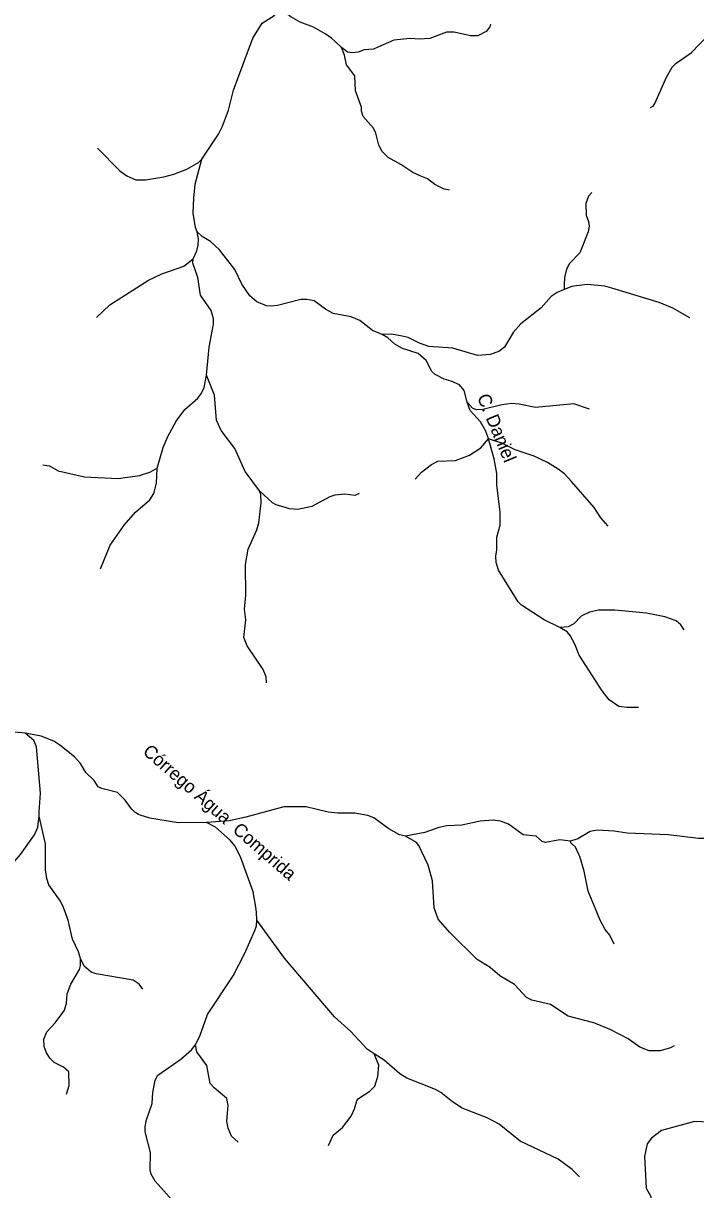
# Model space of a CAD drawing. Extents: x 473.9 to 500, y 7733.1 to 7760.8.
# Drawn here: x 477.9 to 481.99, y 7741.31 to 7748.41 of the extents above; entities that cross this region are included whole.
import ezdxf
from ezdxf.enums import TextEntityAlignment as Align

# ---------------------------------------------------------------- set-up
doc = ezdxf.new("R2010")
doc.units = 0
doc.header["$LTSCALE"] = 0.032
doc.layers.add('61', color=7, linetype='Continuous')
doc.layers.add('7', color=7, linetype='Continuous', lineweight=25)

msp = doc.modelspace()

# ---------------------------------------------------------------- linework, layer by layer
at = {"layer": '7'}
for points in [[(478.9839, 7747.5805), (479.0851, 7747.7324), (479.1095, 7747.7805), (479.1456, 7747.8769), (479.176, 7747.9985), (479.2935, 7748.3153), (479.3509, 7748.4069), (479.4226, 7748.4528), (479.4367, 7748.4688), (479.439, 7748.4833), (479.4278, 7748.51)], [(479.8343, 7748.2586), (479.7962, 7748.2948), (479.7729, 7748.3169), (479.7354, 7748.3421), (479.6641, 7748.3822), (479.5821, 7748.4132), (479.5259, 7748.4455), (479.4621, 7748.4945), (479.4278, 7748.51)], [(480.7404, 7748.4019), (480.7368, 7748.3843), (480.7152, 7748.3569), (480.664, 7748.3307), (480.6197, 7748.3301), (480.5196, 7748.3525), (480.4731, 7748.3532), (480.3712, 7748.3132), (480.3059, 7748.31), (480.2524, 7748.3148), (480.1531, 7748.3044), (480.0553, 7748.2617), (480.0286, 7748.25), (479.9728, 7748.2441), (479.9346, 7748.2314), (479.898, 7748.2267), (479.8705, 7748.2314), (479.8343, 7748.2586)], [(481.7151, 7747.8935), (481.7306, 7747.902), (481.7418, 7747.9179), (481.8131, 7748.078), (481.8468, 7748.1401), (481.8712, 7748.1642), (481.962, 7748.227), (482.0709, 7748.3392)], [(480.4909, 7747.3903), (480.4581, 7747.3968), (480.4029, 7747.425), (480.3579, 7747.46), (480.3175, 7747.477), (480.2684, 7747.4976), (480.1949, 7747.5476), (480.1179, 7747.5898), (480.0814, 7747.6252), (480.0616, 7747.6647), (480.0437, 7747.7371), (480.0297, 7747.7686), (479.9652, 7747.8402), (479.9555, 7747.8715), (479.9554, 7747.8965), (479.9187, 7747.9953), (479.9159, 7748.0862), (479.8643, 7748.1537), (479.8529, 7748.2118), (479.8343, 7748.2586)], [(478.3495, 7747.6474), (478.4855, 7747.5093), (478.5275, 7747.4776), (478.5818, 7747.4545), (478.6415, 7747.4537), (478.7531, 7747.4721), (478.8132, 7747.4882), (478.8919, 7747.5183), (478.9644, 7747.5595), (478.9839, 7747.5805)], [(478.9562, 7747.1379), (478.9452, 7747.1637), (478.9317, 7747.2508), (478.9344, 7747.3428), (478.9429, 7747.4267), (478.9839, 7747.5805)], [(481.3573, 7747.3762), (481.3375, 7747.3538), (481.3221, 7747.3098), (481.324, 7747.2382), (481.3383, 7747.1997), (481.3408, 7747.1715), (481.3353, 7747.1377), (481.2859, 7747.01), (481.2229, 7746.9435), (481.2034, 7746.9095), (481.1909, 7746.8592), (481.1905, 7746.8131), (481.1903, 7746.7868)], [(478.9303, 7746.9724), (478.9533, 7747.0212), (478.9611, 7747.0568), (478.9645, 7747.0933), (478.9562, 7747.1379)], [(480.0823, 7746.5122), (480.022, 7746.5361), (479.945, 7746.5973), (479.8926, 7746.6198), (479.783, 7746.6409), (479.7358, 7746.667), (479.6678, 7746.7162), (479.6239, 7746.7256), (479.5891, 7746.7244), (479.579, 7746.7241), (479.4446, 7746.6889), (479.4052, 7746.6855), (479.377, 7746.6863), (479.3186, 7746.7113), (479.2764, 7746.7479), (479.2282, 7746.8187), (479.184, 7746.9074), (479.0908, 7747.0273), (479.0369, 7747.0782), (478.9854, 7747.1091), (478.9562, 7747.1379)], [(478.3417, 7746.6164), (478.4234, 7746.6923), (478.6596, 7746.8423), (478.7396, 7746.881), (478.874, 7746.9281), (478.9303, 7746.9724)], [(479.0116, 7746.2656), (479.0287, 7746.4345), (479.0494, 7746.5427), (479.0557, 7746.5757), (479.0558, 7746.6085), (479.0415, 7746.6579), (478.9767, 7746.7525), (478.9598, 7746.8596), (478.9293, 7746.9466), (478.9303, 7746.9724)], [(481.1903, 7746.7868), (481.1461, 7746.7678), (481.1101, 7746.7433), (481.0492, 7746.6736), (480.9257, 7746.5773), (480.88, 7746.5236), (480.8271, 7746.4346), (480.791, 7746.4082), (480.7397, 7746.3905), (480.6627, 7746.3841), (480.512, 7746.4298), (480.3661, 7746.4402), (480.3083, 7746.4595), (480.2402, 7746.4932), (480.2025, 7746.5028), (480.1384, 7746.514), (480.0823, 7746.5122)], [(481.9542, 7746.6147), (481.8502, 7746.6728), (481.7676, 7746.708), (481.4801, 7746.7938), (481.4372, 7746.8066), (481.3298, 7746.8163), (481.2474, 7746.8056), (481.2368, 7746.8042), (481.1903, 7746.7868)], [(480.5999, 7746.1013), (480.58, 7746.1723), (480.5523, 7746.205), (480.5014, 7746.2283), (480.459, 7746.2402), (480.4042, 7746.2682), (480.3845, 7746.2865), (480.3497, 7746.3538), (480.3002, 7746.3976), (480.2063, 7746.4279), (480.159, 7746.4543), (480.1166, 7746.4922), (480.0823, 7746.5122)], [(478.712, 7745.6979), (478.7484, 7745.8239), (478.7771, 7745.8924), (478.828, 7745.9848), (478.8801, 7746.0551), (478.9599, 7746.1245), (478.9785, 7746.1485), (478.9981, 7746.1872), (479.0116, 7746.2656)], [(479.3352, 7745.5602), (479.2479, 7745.6783), (479.1845, 7745.8187), (479.1025, 7745.9274), (479.074, 7745.9915), (479.0616, 7746.1432), (479.0116, 7746.2656)], [(480.7298, 7745.8772), (480.713, 7745.9241), (480.6807, 7745.9809), (480.6176, 7746.0492), (480.5999, 7746.1013)], [(481.3431, 7746.058), (481.2482, 7746.0898), (481.0146, 7746.0673), (480.9163, 7746.089), (480.8703, 7746.0915), (480.8105, 7746.0842), (480.6937, 7746.0567), (480.6559, 7746.0546), (480.6317, 7746.0646), (480.5999, 7746.1013)], [(480.2823, 7745.6313), (480.3214, 7745.6738), (480.3823, 7745.7203), (480.4195, 7745.7406), (480.5275, 7745.7463), (480.6132, 7745.7773), (480.6825, 7745.8219), (480.7298, 7745.8772)], [(481.1639, 7744.7282), (481.0676, 7744.7753), (480.9302, 7744.8641), (480.9101, 7744.885), (480.7891, 7745.0777), (480.7747, 7745.1248), (480.7734, 7745.1629), (480.7797, 7745.2019), (480.7798, 7745.2796), (480.8005, 7745.351), (480.8005, 7745.4303), (480.7798, 7745.598), (480.7797, 7745.666), (480.7644, 7745.7558), (480.7298, 7745.8772)], [(481.4576, 7745.3463), (481.4136, 7745.3973), (481.372, 7745.4591), (481.2351, 7745.6178), (481.192, 7745.6632), (481.1535, 7745.6918), (481.0881, 7745.7324), (481.0063, 7745.7708), (480.8922, 7745.8106), (480.8095, 7745.8511), (480.7298, 7745.8772)], [(478.015, 7745.7194), (478.0555, 7745.7136), (478.1092, 7745.6833), (478.2699, 7745.6449), (478.4747, 7745.636), (478.604, 7745.6545), (478.6678, 7745.6752), (478.712, 7745.6979)], [(478.3665, 7745.0863), (478.4255, 7745.2292), (478.5118, 7745.351), (478.5803, 7745.4305), (478.6668, 7745.5068), (478.6917, 7745.5435), (478.7078, 7745.6082), (478.712, 7745.6979)], [(479.3768, 7744.3928), (479.375, 7744.4293), (479.3572, 7744.4737), (479.2605, 7744.6175), (479.2404, 7744.6676), (479.2516, 7744.7764), (479.2436, 7744.8411), (479.2516, 7744.9256), (479.25, 7745.1131), (479.2663, 7745.2048), (479.3187, 7745.3239), (479.3309, 7745.3659), (479.3454, 7745.4868), (479.3421, 7745.539), (479.3352, 7745.5602)], [(479.9424, 7745.5447), (479.9152, 7745.533), (479.8551, 7745.5406), (479.7938, 7745.5342), (479.7628, 7745.5236), (479.653, 7745.4663), (479.5679, 7745.4475), (479.5174, 7745.4508), (479.5052, 7745.4546), (479.4373, 7745.4758), (479.4137, 7745.488), (479.3352, 7745.5602)], [(481.921, 7744.7145), (481.8991, 7744.7449), (481.8718, 7744.7692), (481.8026, 7744.7934), (481.6898, 7744.8158), (481.4971, 7744.8351), (481.3991, 7744.8335), (481.3437, 7744.8225), (481.2922, 7744.7981), (481.2492, 7744.7505), (481.2139, 7744.7323), (481.1639, 7744.7282)], [(481.6423, 7744.2416), (481.5702, 7744.2409), (481.5228, 7744.2483), (481.4633, 7744.2894), (481.4201, 7744.3435), (481.2799, 7744.5595), (481.255, 7744.6268), (481.2269, 7744.6797), (481.2086, 7744.7019), (481.1639, 7744.7282)], [(477.9091, 7744.0852), (477.7182, 7744.103), (477.5626, 7744.1399), (477.3779, 7744.1569), (477.3061, 7744.1712), (477.2072, 7744.2029)], [(477.9926, 7743.5798), (477.9942, 7743.6077), (478.0007, 7743.7196), (477.9766, 7744.0025), (477.9602, 7744.04), (477.9091, 7744.0852)], [(479.0129, 7743.5416), (478.8404, 7743.5394), (478.6664, 7743.5678), (478.6088, 7743.5857), (478.5983, 7743.5913), (478.5786, 7743.6019), (478.5547, 7743.6245), (478.5164, 7743.6786), (478.4705, 7743.7237), (478.3753, 7743.7478), (478.3534, 7743.7587), (478.3275, 7743.797), (478.2778, 7743.8472), (478.245, 7743.9004), (478.2087, 7743.9416), (478.12, 7744.0127), (478.0835, 7744.036), (478.0063, 7744.0677), (477.9091, 7744.0852)], [(480.2235, 7743.4594), (480.1878, 7743.4665), (480.1222, 7743.5032), (480.0306, 7743.57), (479.9934, 7743.5854), (479.9161, 7743.5986), (479.812, 7743.5979), (479.7529, 7743.6039), (479.6191, 7743.6371), (479.4821, 7743.6363), (479.2522, 7743.574), (479.1493, 7743.553), (479.0129, 7743.5416)], [(477.82, 7742.7699), (477.7879, 7742.8106), (477.7771, 7742.8444), (477.7587, 7743.0924), (477.7627, 7743.1596), (477.7808, 7743.218), (477.8021, 7743.2574), (477.8806, 7743.3472), (477.9657, 7743.4661), (477.9848, 7743.514), (477.9926, 7743.5798)], [(478.2456, 7742.7145), (478.2335, 7742.7546), (478.1966, 7742.8315), (478.1707, 7742.9476), (478.1421, 7743.024), (478.1236, 7743.0628), (478.0522, 7743.1627), (478.0405, 7743.2004), (478.0329, 7743.2533), (478.0312, 7743.411), (477.9926, 7743.5798)], [(479.3193, 7742.9473), (479.3172, 7742.9957), (479.3122, 7743.0259), (479.2964, 7743.1208), (479.2193, 7743.3327), (479.1843, 7743.3996), (479.1571, 7743.4349), (479.0674, 7743.5126), (479.0129, 7743.5416)], [(481.2278, 7743.4288), (481.1626, 7743.4367), (481.076, 7743.4207), (481.0562, 7743.4269), (481.0189, 7743.4596), (480.9394, 7743.4666), (480.8499, 7743.5307), (480.8018, 7743.5498), (480.7579, 7743.5569), (480.6791, 7743.5498), (480.5671, 7743.5258), (480.4744, 7743.5215), (480.4272, 7743.5121), (480.341, 7743.4818), (480.2235, 7743.4594)], [(481.8601, 7742.1829), (481.8367, 7742.1695), (481.7735, 7742.1511), (481.7075, 7742.152), (481.6507, 7742.1738), (481.5791, 7742.2244), (481.4702, 7742.2824), (481.3708, 7742.3224), (481.2142, 7742.3623), (481.1062, 7742.4332), (480.9936, 7742.46), (480.96, 7742.4767), (480.8881, 7742.5548), (480.7984, 7742.608), (480.7386, 7742.6591), (480.6592, 7742.7084), (480.4936, 7742.872), (480.4228, 7742.9532), (480.3985, 7743.0234), (480.3885, 7743.1859), (480.3618, 7743.283), (480.3052, 7743.4028), (480.2904, 7743.42), (480.2235, 7743.4594)], [(482.2368, 7743.4441), (482.0066, 7743.4435), (481.8239, 7743.4671), (481.5727, 7743.476), (481.4942, 7743.4897), (481.3935, 7743.496), (481.3486, 7743.4871), (481.273, 7743.4428), (481.2278, 7743.4288)], [(481.4932, 7742.8006), (481.4678, 7742.856), (481.4389, 7742.8905), (481.409, 7742.9479), (481.3365, 7743.123), (481.3121, 7743.2458), (481.2847, 7743.3359), (481.2817, 7743.3423), (481.2587, 7743.3912), (481.2304, 7743.4185), (481.2278, 7743.4288)], [(478.9456, 7742.1881), (478.974, 7742.2481), (479.0185, 7742.3726), (479.1747, 7742.6079), (479.2453, 7742.7458), (479.3073, 7742.8844), (479.3173, 7742.9126), (479.3193, 7742.9473)], [(480.0332, 7742.1333), (479.991, 7742.1616), (479.8903, 7742.2703), (479.7905, 7742.3584), (479.4879, 7742.7154), (479.3193, 7742.9473)], [(478.1602, 7741.8886), (478.1763, 7741.9403), (478.1749, 7742.024), (478.1423, 7742.0533), (478.0845, 7742.0805), (478.0599, 7742.1052), (478.0375, 7742.1397), (478.0234, 7742.1789), (478.0219, 7742.224), (478.0407, 7742.2675), (478.091, 7742.3232), (478.1271, 7742.3714), (478.1482, 7742.3996), (478.1596, 7742.4428), (478.1644, 7742.4983), (478.1869, 7742.5582), (478.2387, 7742.6475), (478.246, 7742.6721), (478.2456, 7742.7145)], [(478.6244, 7742.528), (478.603, 7742.5585), (478.5653, 7742.5817), (478.3408, 7742.6199), (478.3105, 7742.63), (478.2684, 7742.6677), (478.2456, 7742.7145)], [(478.8237, 7741.2052), (478.8022, 7741.2433), (478.6995, 7741.3579), (478.6763, 7741.4023), (478.6692, 7741.427), (478.6711, 7741.5326), (478.639, 7741.658), (478.6382, 7741.6879), (478.6449, 7741.7268), (478.6824, 7741.8322), (478.6863, 7741.8993), (478.6996, 7741.9735), (478.7164, 7742.0043), (478.8564, 7742.1009), (478.9218, 7742.1576), (478.9456, 7742.1881)], [(479.2046, 7741.596), (479.165, 7741.632), (479.144, 7741.6811), (479.1353, 7741.7248), (479.144, 7741.8198), (479.1361, 7741.8626), (479.0581, 7741.9278), (479.0351, 7741.9537), (479.0133, 7742.0627), (478.9538, 7742.1455), (478.9456, 7742.1881)], [(479.7541, 7741.5755), (479.7828, 7741.6386), (479.8407, 7741.6863), (479.8937, 7741.7546), (479.9138, 7741.7995), (479.9264, 7741.8469), (479.9372, 7741.8617), (480.0071, 7741.9071), (480.0377, 7741.9369), (480.0549, 7741.9948), (480.0614, 7742.0639), (480.0332, 7742.1333)], [(481.2828, 7741.3849), (481.2378, 7741.4288), (481.1522, 7741.4917), (480.9225, 7741.6017), (480.7944, 7741.7055), (480.7214, 7741.7436), (480.5683, 7741.8025), (480.5098, 7741.8407), (480.4397, 7741.898), (480.4071, 7741.9161), (480.2314, 7741.9849), (480.1901, 7742.0123), (480.0945, 7742.0959), (480.0332, 7742.1333)], [(482.1099, 7741.7153), (481.984, 7741.7217), (481.7828, 7741.6667), (481.7217, 7741.6213), (481.6941, 7741.5852), (481.6778, 7741.5085), (481.6894, 7741.3158), (481.7178, 7741.266), (481.7194, 7741.228), (481.6886, 7741.1924)]]:
    msp.add_lwpolyline(points, dxfattribs=at)

# ---------------------------------------------------------------- texts
at = {"layer": '61'}
for s, rotation, p in [('C. Daniel', 292.622, (480.7426, 7745.9288)), ('Córrego Água  Comprida', 318.945, (479.067, 7743.5746))]:
    msp.add_text(s, height=0.08, rotation=rotation, dxfattribs=at).set_placement(p, align=Align.CENTER)

doc.saveas('drawing.dxf')
